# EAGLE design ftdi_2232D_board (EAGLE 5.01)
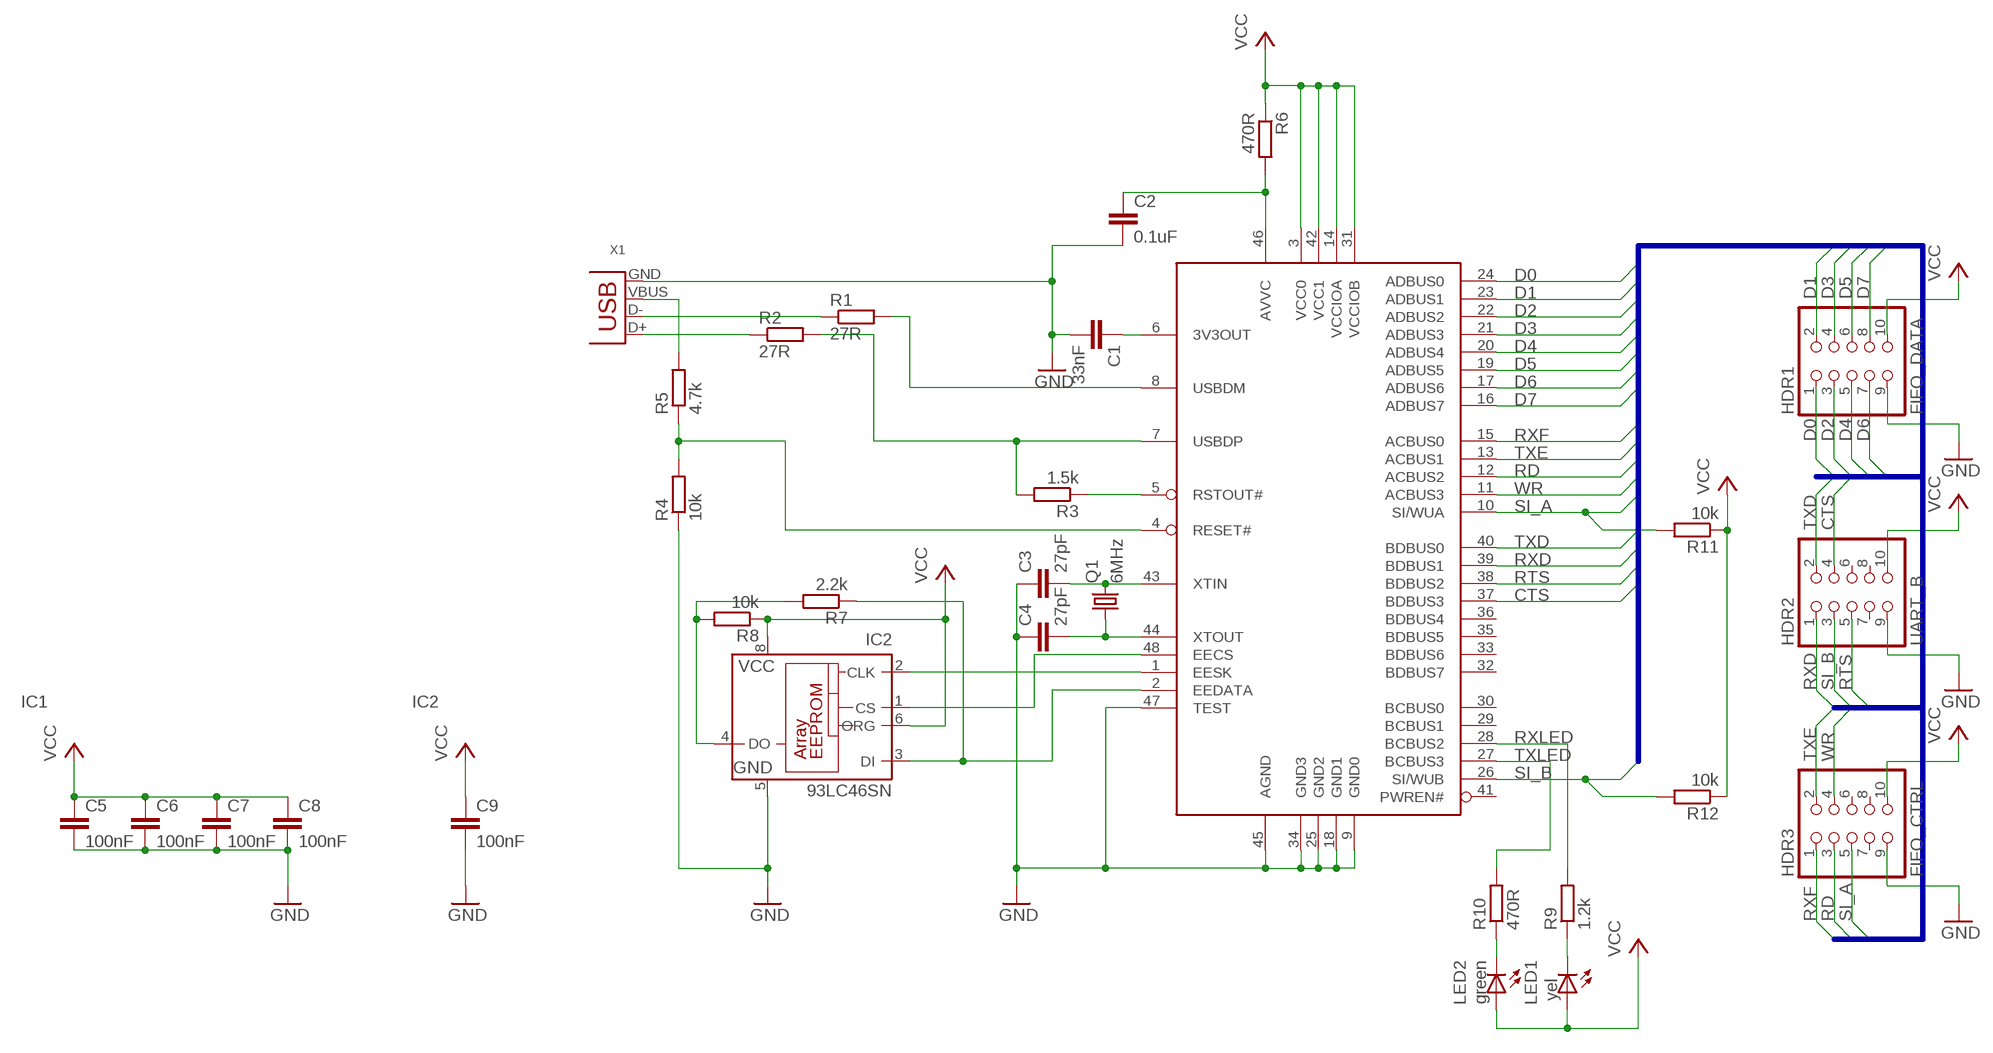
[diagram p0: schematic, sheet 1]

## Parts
C1  33nF  C-EUC0805  [C0805]
C2  0.1uF  C-EUC0805  [C0805]
C3  27pF  C-EUC0805  [C0805]
C4  27pF  C-EUC0805  [C0805]
C5  100nF  C-EUC0805  [C0805]
C6  100nF  C-EUC0805  [C0805]
C7  100nF  C-EUC0805  [C0805]
C8  100nF  C-EUC0805  [C0805]
C9  100nF  C-EUC0805  [C0805]
HDR1  FIFO_DATA  PINHD-2X5  [2X05]
HDR2  UART_B  PINHD-2X5  [2X05]
HDR3  FIFO_CTRL  PINHD-2X5  [2X05]
IC1  FT2232D  FT2232L  [LQFP48]
IC2  93LC46SN  [SO-08]
LED1  yel  LEDSMT1206  [1206]
LED2  green  LEDSMT1206  [1206]
Q1  6MHz  CRYSTALHC49U70  [HC49U70]
R1  27R  R-EU_R0805  [R0805]
R2  27R  R-EU_R0805  [R0805]
R3  1.5k  R-EU_R0805  [R0805]
R4  10k  R-EU_R0805  [R0805]
R5  4.7k  R-EU_R0805  [R0805]
R6  470R  R-EU_R0805  [R0805]
R7  2.2k  R-EU_R0805  [R0805]
R8  10k  R-EU_R0805  [R0805]
R9  1.2k  R-EU_R0805  [R0805]
R10  470R  R-EU_R0805  [R0805]
R11  10k  R-EU_R0805  [R0805]
R12  10k  R-EU_R0805  [R0805]
X1  USBCON  USB-MB-S  [USB-MB-S]

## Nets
3V3OUT: C1.1 IC1.6(3V3OUT)
AVCC: C2.1 IC1.46(AVVC) R6.2
CTS: HDR2.4 IC1.37(BDBUS3)
D0: HDR1.1 IC1.24(ADBUS0)
D1: HDR1.2 IC1.23(ADBUS1)
D2: HDR1.3 IC1.22(ADBUS2)
D3: HDR1.4 IC1.21(ADBUS3)
D4: HDR1.5 IC1.20(ADBUS4)
D5: HDR1.6 IC1.19(ADBUS5)
D6: HDR1.7 IC1.17(ADBUS6)
D7: HDR1.8 IC1.16(ADBUS7)
D+: R2.1 X1.D+
D-: R1.1 X1.D-
EE_DOUT: IC2.4(DO) R7.2 R8.2
EECS: IC1.48(EECS) IC2.1(CS)
EEDATA: IC1.2(EEDATA) IC2.3(DI) R7.1
EESK: IC1.1(EESK) IC2.2(CLK)
GND: C1.2 C2.2 C3.1 C4.1 C5.2 C6.2 C7.2 C8.2 C9.2 HDR1.9 HDR2.9 HDR3.9 IC1.9(GND0) IC1.18(GND1) IC1.25(GND2) IC1.34(GND3) IC1.45(AGND) IC1.47(TEST) IC2.5(GND) R4.1 X1.GND
N$13: LED1.C R9.1
N$14: LED2.C R10.1
RD: HDR3.3 IC1.12(ACBUS2)
RESET: IC1.4(RESET#) R4.2 R5.1
RSTOUT: IC1.5(RSTOUT#) R3.1
RTS: HDR2.5 IC1.38(BDBUS2)
RXD: HDR2.1 IC1.39(BDBUS1)
RXF: HDR3.1 IC1.15(ACBUS0)
RXLED: IC1.28(BCBUS2) R9.2
SI_A: HDR3.5 IC1.10(SI/WUA) R11.2
SI_B: HDR2.3 IC1.26(SI/WUB) R12.2
TXD: HDR2.2 IC1.40(BDBUS0)
TXE: HDR3.2 IC1.13(ACBUS1)
TXLED: IC1.27(BCBUS3) R10.2
USBDM: IC1.8(USBDM) R1.2
USBDP: IC1.7(USBDP) R2.2 R3.2
VBUS: R5.2 X1.VBUS
VCC: C5.1 C6.1 C7.1 C8.1 C9.1 HDR1.10 HDR2.10 HDR3.10 IC1.3(VCC0) IC1.14(VCCIOA) IC1.31(VCCIOB) IC1.42(VCC1) IC2.6(ORG) IC2.8(VCC) LED1.A LED2.A R6.1 R8.1 R11.1 R12.1
WR: HDR3.4 IC1.11(ACBUS3)
XTIN: C3.2 IC1.43(XTIN) Q1.2
XTOUT: C4.2 IC1.44(XTOUT) Q1.1
Unconnected: HDR2.6 HDR2.7 HDR2.8 HDR3.6 HDR3.7 HDR3.8 IC1.29(BCBUS1) IC1.30(BCBUS0) IC1.32(BDBUS7) IC1.33(BDBUS6) IC1.35(BDBUS5) IC1.36(BDBUS4) IC1.41(PWREN#) IC2.7(NU)

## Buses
D[0..7],RXF,TXE,RD,WR,SI_A,TXD,RXD,RTS,CTS,SI_B

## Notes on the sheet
- IC1 | IC2

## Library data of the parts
C1-C9 = rcl:C-EU: CAPACITOR, European symbol
HDR1-HDR3 = pinhead:PINHD-2X5: PIN HEADER
IC1 = ftdichip-3:FT2232L: USB UART / FIFO Controller 3nd Generation USB Double-UART (USB <-> Serial) - FIFO Controller
IC2 = microchip:93*: Serial EPROM 1 K/2 K/4 K, low voltage, Microwire
LED1 LED2 = led:LED: LED
Q1 = crystal:CRYSTAL: CRYSTAL
R1-R12 = rcl:R-EU_: RESISTOR, European symbol
X1 = con-usb-3:USB: USB Connectors

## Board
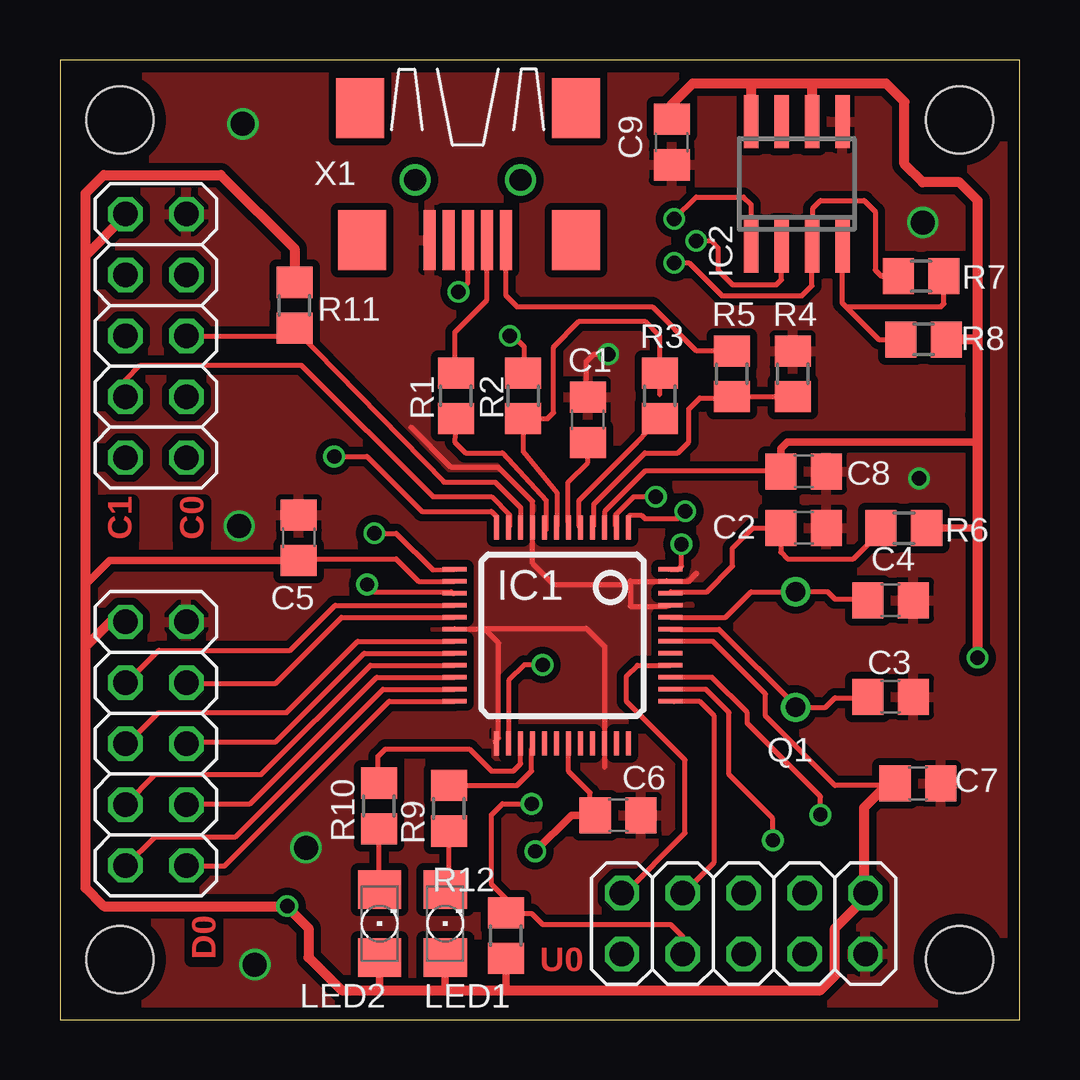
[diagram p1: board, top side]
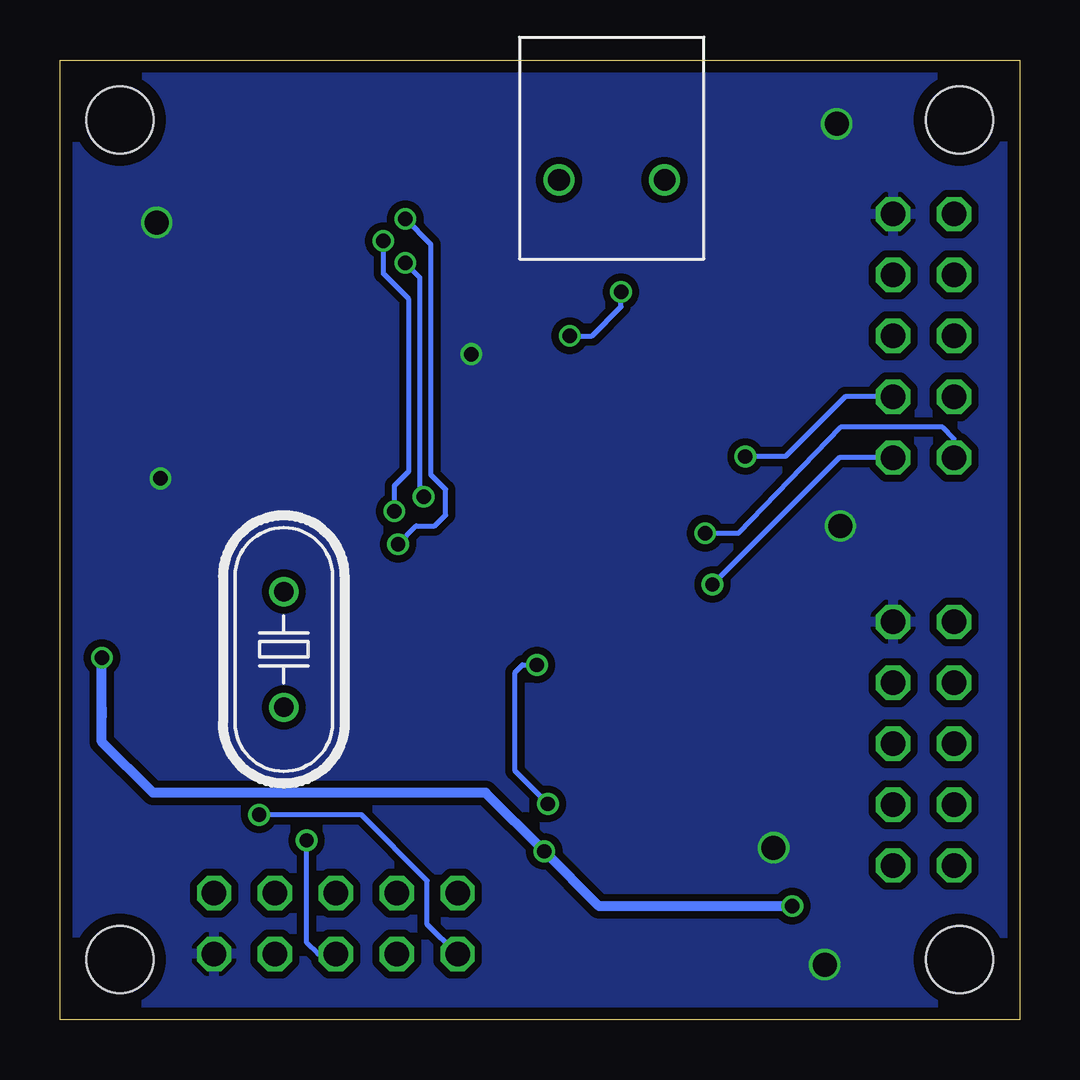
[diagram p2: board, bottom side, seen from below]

Size 40 x 40 mm. Coordinates in mm from the lower left corner, seen from the top.
Outline: 0,0 40,0 40,40 0,40 0,0
Copper layers (1*16): Top 0.035mm / dielectric 1.5mm / Bottom 0.035mm
Design rules "PCB-POOL *": minimum track width 6mil, minimum drill 12mil, track to track 8mil, track to pad 8mil, pad to pad 8mil, via to via 8mil, smd to smd 6mil, copper to edge 20mil, drill to drill 8mil, minimum pad ring 8mil, minimum via ring 6mil, stop-mask expansion 3mil, vias tented up to drill 0mil, thermal gap 8mil
Holes 2.8 mm at 2.5,37.5 37.5,37.5 37.5,2.5 2.5,2.5

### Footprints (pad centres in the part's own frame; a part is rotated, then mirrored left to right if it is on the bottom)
C0805 = smd 1.3 x 1.5: 1 -0.95,0; 2 0.95,0
2X05 = drill 1.016 octagon: 1 -5.08,-1.27; 2 -5.08,1.27; 3 -2.54,-1.27; 4 -2.54,1.27; 5 0,-1.27; 6 0,1.27; 7 2.54,-1.27; 8 2.54,1.27; 9 5.08,-1.27; 10 5.08,1.27
LQFP48 = smd 0.2 x 1: 1 -2.75,-4.5; 2 -2.25,-4.5; 3 -1.75,-4.5; 4 -1.25,-4.5; 5 -0.75,-4.5; 6 -0.25,-4.5; 7 0.25,-4.5; 8 0.75,-4.5; 9 1.25,-4.5; 10 1.75,-4.5; 11 2.25,-4.5; 12 2.75,-4.5; 25 2.75,4.5; 26 2.25,4.5; 27 1.75,4.5; 28 1.25,4.5; 29 0.75,4.5; 30 0.25,4.5; 31 -0.25,4.5; 32 -0.75,4.5; 33 -1.25,4.5; 34 -1.75,4.5; 35 -2.25,4.5; 36 -2.75,4.5 | smd 1 x 0.2: 13 4.5,-2.75; 14 4.5,-2.25; 15 4.5,-1.75; 16 4.5,-1.25; 17 4.5,-0.75; 18 4.5,-0.25; 19 4.5,0.25; 20 4.5,0.75; 21 4.5,1.25; 22 4.5,1.75; 23 4.5,2.25; 24 4.5,2.75; 37 -4.5,2.75; 38 -4.5,2.25; 39 -4.5,1.75; 40 -4.5,1.25; 41 -4.5,0.75; 42 -4.5,0.25; 43 -4.5,-0.25; 44 -4.5,-0.75; 45 -4.5,-1.25; 46 -4.5,-1.75; 47 -4.5,-2.25; 48 -4.5,-2.75
SO-08 = smd 0.6 x 2.2: 1 -1.905,-2.6; 2 -0.635,-2.6; 3 0.635,-2.6; 4 1.905,-2.6; 5 1.905,2.6; 6 0.635,2.6; 7 -0.635,2.6; 8 -1.905,2.6
1206 = smd 1.6 x 1.803: A -1.422,0; C 1.422,0
HC49U70 = drill 0.813 round: 1 -2.413,0; 2 2.413,0
R0805 = smd 1.3 x 1.5: 1 -0.95,0; 2 0.95,0
USB-MB-S = smd 2.5 x 0.5: D+ 2.5,0; D- 2.5,0.8; GND 2.5,-1.6; ID 2.5,-0.8; VBUS 2.5,1.6 | smd 2.5 x 2: P$1 -3,-4.5; P$2 -3,4.5; P$3 2.5,-4.4; P$4 2.5,4.5 | drill 0.9 round: P$5 0,2.2; P$6 0,-2.2

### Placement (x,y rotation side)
C1  22,25 90 top
C2  31,20.5 0 top
C3  34.63,13.46 180 top
C4  34.63,17.48 180 top
C5  9.96,20.09 90 top
C6  23.27,8.52 0 top
C7  35.76,9.84 0 top
C8  31,22.85 0 top
C9  25.5,36.58 270 top
HDR1  4,11.5 90 top
HDR2  28.5,4 0 top
HDR3  4,28.5 90 top
IC1  20.95,16.02 180 top
IC2  30.71,34.83 0 top
LED1  16.06,4 90 top
LED2  13.32,4 90 top
Q1  30.67,15.42 270 bottom
R1  16.5,26 270 top
R2  19.3,26 270 top
R3  25,26 90 top
R4  30.54,26.91 270 top
R5  28,26.91 90 top
R6  35.17,20.48 180 top
R7  35.9,30.99 0 top
R8  36,28.35 180 top
R9  16.21,8.8 90 top
R10  13.29,8.9 90 top
R11  9.77,29.78 270 top
R12  18.59,3.5 90 top
X1  17,35 270 top

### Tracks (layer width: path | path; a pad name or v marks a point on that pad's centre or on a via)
3V3OUT
  Top 0.203: C1.1 22,23.22 21.18,22.4 21.18,20.73 21.2,20.71 IC1.6
AVCC
  Top 0.203: IC1.46 25.45,17.83 26.98,17.83 28.04,18.9 28.04,19.66 28.88,20.5 C2.1 30.05,19.48 30.33,19.2 33.07,19.2 34.29,20.42 34.23,20.48 R6.2
CTS
  Top 0.203: HDR2.4 26,5.27 27.28,6.55 27.28,12.65 26.67,13.26 25.6,13.26 25.59,13.27 IC1.37
D0
  Top 0.203: IC1.24 13.72,13.27 6.86,6.4 5.33,6.4 5.32,6.42 HDR1.1
D1
  Top 0.203: IC1.23 13.46,13.77 7.32,7.62 3.96,7.62 2.74,6.4 HDR1.2
D2
  Top 0.203: IC1.22 13.2,14.27 7.92,8.99 5.33,8.99 5.3,8.96 HDR1.3
D3
  Top 0.203: IC1.21 12.94,14.77 8.38,10.21 3.96,10.21 2.73,8.98 HDR1.4
D4
  Top 0.203: IC1.20 12.68,15.27 8.99,11.58 5.49,11.58 5.33,11.43 HDR1.5
D5
  Top 0.203: IC1.19 12.41,15.77 9.45,12.8 4.12,12.8 2.74,11.43 2.73,11.44 HDR1.6
D6
  Top 0.203: IC1.17 11.74,16.77 8.99,14.02 5.18,14.02 5.2,14.04 HDR1.7
D7
  Top 0.203: IC1.16 11.48,17.27 9.6,15.39 4.12,15.39 2.74,14.02 HDR1.8
D+  (via drill 0.6)
  Top 0.203: X1.D+ 17,30.72 v16.61,30.33 | v18.75,28.5 18.9,28.5 19.36,28.04 19.36,27.13 19.3,27.08 R2.1
  Bottom 0.203: v16.61,30.33 16.61,29.72 17.83,28.5 v18.75,28.5
D-
  Top 0.203: X1.D- 17.8,29.99 16.46,28.65 16.46,27.13 16.5,27.09 R1.1
EE_DOUT
  Top 0.203: R8.2 34.13,28.35 32.61,29.87 | IC2.4 32.62,32.01 32.61,32 32.61,29.87 | R7.2 36.85,29.84 36.73,29.72 32.77,29.72 32.61,29.87
EECS  (via drill 0.6)
  Top 0.203: IC2.1 28.81,33.98 28.5,34.29 26.52,34.29 v25.6,33.38 | IC1.48 25.78,18.77 25.91,18.9 v25.91,19.81
  Bottom 0.203: v25.6,33.38 24.54,32.31 24.54,22.71 23.93,22.1 23.93,21.03 24.38,20.57 25.15,20.57 v25.91,19.81
EEDATA  (via drill 0.6)
  Top 0.203: v24.84,21.79 23.93,21.79 23.16,21.03 23.16,20.57 23.2,20.54 IC1.2 | R7.1 34.24,30.99 33.98,31.24 33.98,33.68 33.53,34.14 31.7,34.14 31.39,33.83 31.39,32.46 31.35,32.42 IC2.3 31.35,30.59 30.94,30.18 27.58,30.18 26.21,31.55 v25.6,31.55
  Bottom 0.203: v24.84,21.79 24.99,21.95 24.99,30.94 v25.6,31.55
EESK  (via drill 0.6)
  Top 0.203: IC2.2 30.08,30.84 29.87,30.63 28.04,30.63 27.43,31.24 27.43,32.16 27.13,32.46 v26.52,32.46 | IC1.1 23.7,20.95 23.77,21.03 24.23,21.03 24.38,20.88 25.76,20.88 v26.06,21.18
  Bottom 0.203: v26.06,21.18 26.06,22.25 25.45,22.86 25.45,30.02 26.52,31.09 v26.52,32.46
GND  (via drill 0.6, 1)
  Top 0.203: 25.3,18.29 25.32,18.27 IC1.47 | v22.86,27.74 22.25,27.74 21.95,27.43 21.95,26.06 22,26.01 C1.2 | IC1.34 | 14.63,24.69 16.31,23.01 18.29,23.01 19.7,21.6 IC1.9 19.7,19.01 20.57,18.14 23.62,18.14 23.77,18.29 | IC1.47 26.19,18.27 | IC1.47 23.79,18.27 23.77,18.29 | 23.77,18.29 23.77,17.22 25.3,17.22 25.34,17.27 IC1.45 | 17.68,16.27 17.72,16.27 18.29,15.7 18.29,11.73 18.14,11.58 IC1.25 | 17.68,16.27 IC1.18 16.45,16.3 | 17.68,16.27 17.68,16.31 21.95,16.31 22.7,15.55 IC1.34 | IC1.34 22.7,10.53 22.71,10.52 22.71,11.73 22.7,11.73 IC1.34
  Top 0.254: 26.19,18.27 26.52,18.59
  other vias: 35.97,33.22 7.62,37.34 10.25,7.16 7.47,20.57 8.12,2.29 35.81,22.56
  pour Top (isolate 0.305): -1.98,41.91 42.21,41.91 42.21,-2.29 -2.29,-2.29 -2.29,41.91
  pour Bottom (isolate 0.305): -1.07,40.84 40.84,40.84 40.84,-0.91 -1.07,-0.91
N$13
  Top 0.203: LED1.C 16.06,5.55 16.21,5.7 R9.1
N$14
  Top 0.203: LED2.C 13.32,5.55 13.41,5.64 13.29,5.76 R10.1
RD  (via drill 0.6)
  Top 0.203: IC1.12 18.2,20.97 17.98,21.18 15.09,21.18 12.8,23.47 v11.43,23.47
  Bottom 0.203: HDR3.3 7.26,25.96 9.75,23.47 v11.43,23.47
RESET
  Top 0.203: 30.58,25.96 R4.2 | 30.58,25.96 R5.1 27.95,25.96 27.89,25.91 26.67,25.91 26.21,25.45 26.21,24.08 25.76,23.62 24.38,23.62 22.25,21.49 22.25,20.57 IC1.4 | 30.58,25.96 30.63,25.91
RSTOUT
  Top 0.203: R3.1 24.05,24.05 21.64,21.64 21.64,20.57 IC1.5
RTS  (via drill 0.6)
  Top 0.203: IC1.38 26.92,13.77 27.89,12.8 27.89,10.21 29.72,8.38 v29.72,7.47
  Bottom 0.203: HDR2.5 29.25,2.73 29.72,3.2 v29.72,7.47
RXD  (via drill 0.6)
  Top 0.203: IC1.39 27.18,14.27 28.65,12.8 28.65,12.34 31.7,9.3 v31.7,8.53
  Bottom 0.203: v31.7,8.53 27.43,8.53 24.69,5.79 24.69,3.96 23.46,2.73 HDR2.1
RXF  (via drill 0.6)
  Top 0.203: v12.8,18.14 13.11,17.83 16.31,17.83 16.37,17.77 IC1.15
  Bottom 0.203: HDR3.1 7.52,23.42 v12.8,18.14
RXLED
  Top 0.203: R9.2 19.05,9.76 19.66,10.36 19.66,11.28 19.7,11.32 IC1.28
SI_A
  Top 0.203: HDR3.5 9.45,28.5 9.75,28.8 | IC1.10 19.2,21.34 18.14,22.4 16,22.4 9.75,28.8 | 9.75,28.8 R11.2
SI_B  (via drill 0.6)
  Top 0.203: IC1.26 18.7,14.13 19.36,14.78 v20.12,14.78 | HDR2.3 25.96,3.45 25.45,3.96 20.12,3.96 19.66,4.42 18.59,4.42 18.59,4.43 R12.2 | R12.2 18.71,4.45 | v19.66,8.99 18.44,8.99 17.98,8.53 17.98,5.64 18.59,5.03 18.59,4.27 R12.2 | 18.59,4.57 R12.2
  Bottom 0.203: v20.12,14.78 20.73,14.78 21.03,14.48 21.03,10.36 v19.66,8.99
TXD
  Top 0.203: IC1.40 24.06,14.77 23.62,14.33 23.62,13.26 26.06,10.82 26.06,7.77 23.47,5.18 23.42,5.23 HDR2.2
TXE  (via drill 0.6)
  Top 0.203: IC1.13 16.02,18.77 15.54,18.75 14.02,20.27 v13.11,20.27
  Bottom 0.203: HDR3.2 2.73,24.22 3.2,24.69 7.47,24.69 11.73,20.27 v13.11,20.27
TXLED
  Top 0.203: IC1.27 19.2,10.66 18.9,10.36 17.98,10.36 17.07,11.28 13.56,11.28 13.26,10.97 13.26,9.91 13.29,9.87 R10.2
USBDM
  Top 0.203: R1.2 16.46,24.08 16.92,23.62 18.44,23.62 20.27,21.64 20.27,20.42 20.2,20.49 IC1.8
USBDP
  Top 0.203: IC1.7 20.7,20.55 20.73,20.57 20.73,21.95 19.3,23.67 R2.2 20.33,25.05 20.57,25.3 20.57,28.04 21.64,29.11 24.38,29.11 24.99,28.5 24.99,26.06 25,26.05 R3.2
VBUS
  Top 0.203: X1.VBUS 18.6,30.17 19.05,29.72 24.69,29.72 26.52,27.89 27.89,27.89 28,27.78 | 28,27.78 28.04,27.74 | 28,27.78 R5.2
VCC  (via drill 0.6)
  Top 0.203: IC1.42 27.21,15.77 29.41,13.56 29.41,12.65 32.31,9.75 34.9,9.75 | IC1.14 14.96,18.27 14.02,19.2 9.45,19.2 9.38,19.14 C5.1 | IC1.31 21.2,10.35 22.1,9.45 22.1,8.53 22.11,8.52 C6.1 | IC1.3 22.7,21.17 24.38,22.86 30.02,22.86 30.04,22.85 C8.1
  Top 0.305: LED2.A 13.32,1.28 13.26,1.22 | LED1.A 16.06,1.28 16,1.22 | R12.1 18.59,1.23 18.59,1.22 | 38.25,25.15 38.2,25.2 | C5.1 2.07,19.14 1.07,18.14 | C6.1 21.32,8.52 v19.81,7.01 | R6.1 38.2,20.48 38.25,20.42 | C8.1 30.05,23.8 30.33,24.08 38.25,24.08
  Top 0.406: HDR1.10 2.1,16.58 1.07,15.54 | 1.07,15.54 1.07,5.49 1.83,4.72 9.45,4.72 | HDR3.10 2.73,33.54 2.74,33.53 1.07,31.85 1.07,31.7 | 1.07,15.54 1.07,18.14 1.07,31.7 | R11.1 9.77,32.14 6.71,35.2 1.83,35.2 1.07,34.44 1.07,31.7 | v38.25,15.09 38.25,20.42 38.25,24.08 38.25,25.15 38.25,28.35 | 26.36,1.22 18.59,1.22 16,1.22 13.26,1.22 11.73,1.22 10.36,2.59 10.36,3.81 9.45,4.72 | 26.36,1.22 26.52,1.22 | 9.45,4.72 v9.47,4.72 | 38.25,28.35 36.88,28.35 36.88,28.19 36.95,28.26 R8.1 | 38.25,28.35 38.25,34.14 37.49,34.9 35.97,34.9 35.2,35.66 35.2,38.25 34.44,39.01 31.24,39.01 | 31.24,39.01 29.72,39.01 | 29.72,39.01 29.41,39.01 | C9.1 25.5,38.15 26.36,39.01 28.8,39.01 | 29.72,39.01 28.8,39.01 | 28.8,39.01 28.8,38.86 28.81,38.86 IC2.8 | IC2.6 31.35,38.91 31.24,39.01 | 34.9,9.75 34.9,10.06 | 34.98,9.98 35.05,10.06 | 34.98,9.98 34.84,9.84 | 34.9,9.75 34.44,9.75 33.53,8.84 33.53,5.33 33.58,5.28 HDR2.10 33.59,5.27 33.68,5.18 32.31,3.81 32.31,1.83 31.7,1.22 26.36,1.22 | 34.66,9.84 34.59,9.91 | 34.66,9.84 C7.1 34.81,9.97 34.9,10.06 | 34.9,9.75 34.75,9.75 34.66,9.84 | 34.9,10.06 34.98,9.98
  Bottom 0.406: 38.25,12.95 v38.25,15.09 | 38.25,12.95 38.25,12.65 | v9.47,4.72 17.53,4.72 v19.81,7.01 22.25,9.45 36.12,9.45 38.25,11.58 38.25,12.95
WR
  Top 0.203: HDR3.4 2.73,26.66 3.35,27.28 10.06,27.28 15.54,21.79 17.98,21.79 18.75,21.03 18.75,20.57 IC1.11
XTIN
  Top 0.203: IC1.43 27.47,16.27 30.67,13.07 Q1.2 31.91,13.01 32.31,13.41 33.68,13.41 C3.2
XTOUT
  Top 0.203: IC1.44 27.74,16.77 28.8,17.83 30.63,17.83 30.64,17.84 Q1.1 32,17.84 32.31,17.53 33.53,17.53 33.68,17.38 | 33.68,17.38 33.68,17.37 | 33.68,17.38 C4.2

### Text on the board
Top: C1 | C0 | D0 | U0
